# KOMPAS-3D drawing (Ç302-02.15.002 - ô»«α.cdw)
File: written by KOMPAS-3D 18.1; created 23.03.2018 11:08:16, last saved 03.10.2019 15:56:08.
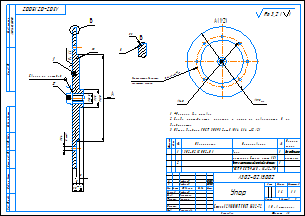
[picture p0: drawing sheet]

Sheet 1: A3, landscape

Document properties: Автор: Милов; Организация: Милов; Полное имя файла: D:\Мембранные насосы\Мембранный электропривод\А302-00.00.000 - ASTRA-302 (МЭ200)\Чертежи ПВХ\А302-02.15.002 - Упор.cdw; Масса: 1.60099; Параметр неуказанной шероховатости: Ra 3,2

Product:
- Part/product: (unnamed)
  - Component: Упор / (материал Сталь лист 15)  | designation А302-02.15.002-01  | pos. 0  | Раздел спецификации: Детали; Примечание: Без отдельного / чертежа
  - Component: Болт с шестигранной головкой с фланцем  / ГОСТ Р 55739-М8 x 16-A2-70  | pos. 0  | Раздел спецификации: Детали

Title block, sheet 1: Наименование: Упор; designation: А302-02.15.002; Материал: Сталь 12Х18Н10Т ГОСТ 5632-72; Масса: 1,6; scale: 1:1; Количество листов документа: 1; organisation: АО «Астерион»; Форматы листов документа: A3; stored path: \\192.168.87.28\Konstructor_doc\Мембранные насосы\Мембранный электропривод\А302-00.00.000 - ASTRA-302 (МЭ200)\Чертежи\А302-00.15.002 - Упор.cdw; Разработал: Лифлянд; Проверил: Борисенко; Т. контр.: Лучихин; Утвердил: Григорьева

Views: Вид 4, Местный разрез 1, Спереди, Вид по стрелке 5, Выносной элемент 6, Вид по стрелке А, Выносной элемент Б, Выносной элемент
Referenced files in D:\Мембранные насосы\Мембранный электропривод\А302-00.00.000 - ASTRA-302 (МЭ200)\3Д ПВХ\: А302-01.15.002 - Упор.a3d, А302-01.15.002 - Упор.m3d
Referenced files in C:\Program Files\ASCON\KOMPAS-3D v18\Libs\PartLib\DATA\VAULT\methods\kompas\3d\: PLib_Bolt_1_ISO_1100.m3d
Referenced files in C:\Program Files\ASCON\KOMPAS-3D V16\Libs\PartLib\DATA\vault\Methods\Kompas\3D\: PLib_Bolt_1_ISO_1100.m3d
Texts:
  Сварка по контуру
  Ra 1,6
  допускается диаметр
  очертить резцом
  для разметки
  Ra 3,2
  Ra 3,2 ( )
  Болт с шестигранной головкой с фланцем ГОСТ Р 55739-М8 x 16-A2-70
Dimensions and other numbers on the sheet: 13,5; 5,6; 8 отв.; 15; 25; 5; 120; 1; 2; 195; 140; 3; 1:1; 1,6; 20.09.2109; 03.10.2019

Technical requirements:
  *Размеры для справок.
  Следы инструмента, царапины и риски на поверхности  В  не
  допускаются.
  Общие допуски ГОСТ 30893.2-mK (H14, h14,  t2/2).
